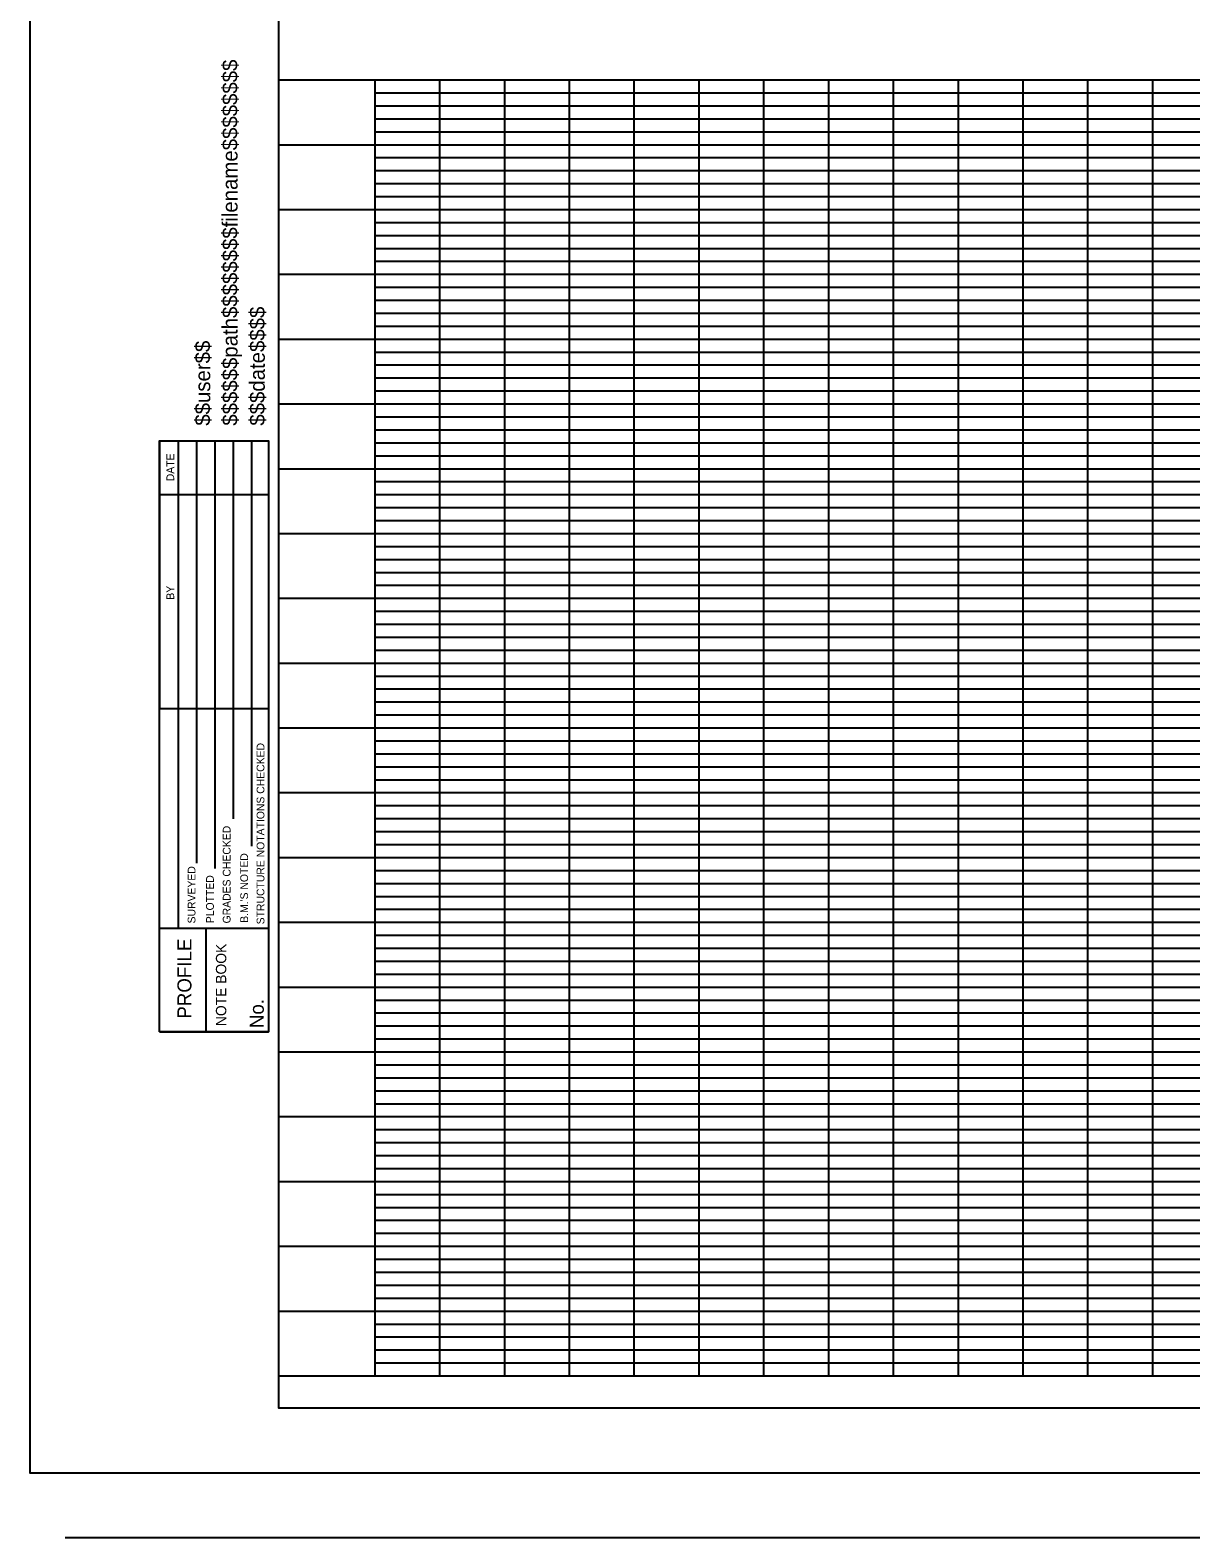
# Model space of a CAD drawing. Extents: x -183 to 1613, y -563 to 588.
# Drawn here: x -183 to 265, y -563 to 19 of the extents above; entities that cross this region are included whole.
import ezdxf

# ---------------------------------------------------------------- set-up
doc = ezdxf.new("R2010")
doc.units = 0
for name, color, linetype in [('RD_SHT_Bndy', 7, 'Continuous'), ('RD_SHT_ID', 7, 'Continuous'), ('RD_SHT_Iplotshp', 7, 'Continuous'), ('RD_SHT_MjGrid', 7, 'Continuous'), ('RD_SHT_MnGrid', 7, 'Continuous'), ('RD_SHT_SubGrid', 7, 'Continuous'), ('RD_SHT_TX', 7, 'Continuous')]:
    doc.layers.add(name, color=color, linetype=linetype)

msp = doc.modelspace()

# ---------------------------------------------------------------- linework, layer by layer
at = {"layer": 'RD_SHT_Bndy'}
for p, q in [((-87, 0), (1588, 0)), ((-50, 0), (-50, -500)), ((-132.95, -139.3), (-132.95, -242.5)), ((-125.85, -139.3), (-125.85, -327.25)), ((-118.8, -139.3), (-118.8, -302.2)), ((-111.7, -139.3), (-111.7, -304.2)), ((-104.65, -139.3), (-104.65, -285.1)), ((-97.55, -139.3), (-97.55, -295.65)), ((-132.95, -159.95), (-90.95, -159.95)), ((-132.95, -242.5), (-90.95, -242.5)), ((-132.95, -327.3), (-90.95, -327.3)), ((-132.95, -367.3), (-132.95, -327.3)), ((-114.95, -367.3), (-114.95, -327.3)), ((-132.95, -367.3), (-90.95, -367.3)), ((-87, -500), (1588, -500)), ((1590.65, -537.5), (-169.35, -537.5)), ((1590.65, -562.5), (-169.35, -562.5))]:
    msp.add_line(p, q, dxfattribs=at)
for points in [[(-86.95, 537.5), (1588, 537.5), (1588, -512.5), (-86.95, -512.5)], [(-132.95, -367.3), (-132.95, -139.3), (-90.95, -139.3), (-90.95, -367.3)]]:
    msp.add_lwpolyline(points, close=True, dxfattribs=at)
at = {"layer": 'RD_SHT_Iplotshp'}
msp.add_lwpolyline([(-182.9, 562.5), (1613, 562.5), (1613, -537.5), (-182.9, -537.5)], close=True, dxfattribs=at)
at = {"layer": 'RD_SHT_MjGrid'}
for p, q in [((0, 0), (0, -500)), ((50, 0), (50, -500)), ((100, 0), (100, -500)), ((150, 0), (150, -500)), ((200, 0), (200, -500)), ((250, 0), (250, -500)), ((-87, -50), (1588, -50)), ((-87, -100), (1588, -100)), ((-87, -150), (1588, -150)), ((-87, -200), (1588, -200)), ((-87, -250), (1588, -250)), ((-87, -300), (1588, -300)), ((-87, -350), (1588, -350)), ((-87, -400), (1588, -400)), ((-87, -450), (1588, -450))]:
    msp.add_line(p, q, dxfattribs=at)
at = {"layer": 'RD_SHT_MnGrid'}
for p, q in [((-25, 0), (-25, -500)), ((25, 0), (25, -500)), ((75, 0), (75, -500)), ((125, 0), (125, -500)), ((175, 0), (175, -500)), ((225, 0), (225, -500)), ((-87, -25), (1588, -25)), ((-87, -75), (1588, -75)), ((-87, -125), (1588, -125)), ((-87, -175), (1588, -175)), ((-87, -225), (1588, -225)), ((-87, -275), (1588, -275)), ((-87, -325), (1588, -325)), ((-87, -375), (1588, -375)), ((-87, -425), (1588, -425)), ((-87, -475), (1588, -475))]:
    msp.add_line(p, q, dxfattribs=at)
at = {"layer": 'RD_SHT_SubGrid'}
for p, q in [((-49.95, -5), (1549.8, -5)), ((-49.95, -10), (1549.25, -10)), ((-49.95, -15), (1549.8, -15)), ((-49.9, -20), (1549.8, -20)), ((-49.95, -30), (1549.8, -30)), ((-49.95, -35), (1548.75, -35)), ((-49.95, -40), (1549.25, -40)), ((-49.95, -45), (1549.8, -45)), ((-49.95, -55), (1549.8, -55)), ((-49.95, -60), (1549.8, -60)), ((-49.95, -65), (1549.25, -65)), ((-49.95, -70), (1549.8, -70)), ((-49.95, -80), (1548.75, -80)), ((-49.95, -85), (1548.75, -85)), ((-49.95, -90), (1549.25, -90)), ((-49.95, -95), (1549.25, -95)), ((-49.95, -105), (1548.75, -105)), ((-49.95, -110), (1549.25, -110)), ((-49.95, -115), (1548.75, -115)), ((-49.9, -120), (1549.8, -120)), ((-49.95, -130), (1549.25, -130)), ((-49.95, -135), (1549.25, -135)), ((-49.95, -140), (1549.25, -140)), ((-49.95, -145), (1549.25, -145)), ((-49.85, -155), (1548.75, -155)), ((-49.85, -160), (1548.75, -160)), ((-49.9, -165), (1549.25, -165)), ((-49.9, -170), (1549.25, -170)), ((-49.95, -180), (1549.25, -180)), ((-49.95, -185), (1549.25, -185)), ((-49.95, -190), (1548.75, -190)), ((-49.95, -195), (1549.25, -195)), ((-49.95, -195), (1549.25, -195)), ((-49.95, -205), (1549.8, -205)), ((-49.95, -210), (1549.8, -210)), ((-49.95, -215), (1549.8, -215)), ((-49.95, -220), (1549.8, -220)), ((-49.95, -230), (1549.8, -230)), ((-49.95, -235), (1549.8, -235)), ((-49.95, -240), (1549.8, -240)), ((-49.95, -245), (1549.8, -245)), ((-49.95, -255), (1549.85, -255)), ((-49.95, -260), (1549.85, -260)), ((-49.95, -265), (1549.85, -265)), ((-49.95, -270), (1549.85, -270)), ((-49.95, -280), (1549.85, -280)), ((-49.95, -285), (1549.85, -285)), ((-49.95, -290), (1549.85, -290)), ((-49.95, -295), (1549.85, -295)), ((-49.95, -305), (1549.85, -305)), ((-49.95, -310), (1549.85, -310)), ((-49.95, -315), (1549.85, -315)), ((-49.95, -320), (1549.85, -320)), ((-49.95, -330), (1549.85, -330)), ((-49.9, -330), (1549.85, -330)), ((-49.95, -335), (1549.85, -335)), ((-49.9, -340), (1549.6, -340)), ((-49.9, -345), (1549.6, -345)), ((-49.95, -360), (1549.95, -360)), ((-49.9, -355), (1549.8, -355)), ((-49.95, -365), (1549.95, -365)), ((-49.9, -370), (1549.95, -370)), ((-49.95, -380), (1549.95, -380)), ((-49.95, -385), (1549.95, -385)), ((-49.95, -390), (1549.95, -390)), ((-49.9, -395), (1549.95, -395)), ((-49.95, -405), (1549.95, -405)), ((-49.95, -410), (1549.95, -410)), ((-49.95, -415), (1549.95, -415)), ((-49.95, -420), (1549.85, -420)), ((-49.9, -430), (1549.6, -430)), ((-49.95, -435), (1549.85, -435)), ((-49.95, -440), (1549.85, -440)), ((-49.95, -445), (1549.85, -445)), ((-49.85, -455), (1549.85, -455)), ((-49.95, -460), (1549.85, -460)), ((-49.95, -465), (1549.85, -465)), ((-49.95, -470), (1549.85, -470)), ((-49.85, -480), (1549.85, -480)), ((-49.85, -485), (1549.85, -485)), ((-49.85, -490), (1549.85, -490)), ((-49.85, -495), (1549.85, -495))]:
    msp.add_line(p, q, dxfattribs=at)

# ---------------------------------------------------------------- texts
at = {"layer": 'RD_SHT_ID'}
for s, p in [('$$$$$$path$$$$$$$$filename$$$$$$$$', (-102.91, -133.42)), ('$$$date$$$$', (-92.39, -133.42)), ('$$user$$', (-113.44, -133.42))]:
    msp.add_text(s, height=5.88, rotation=90, dxfattribs=at).set_placement(p)
at = {"layer": 'RD_SHT_TX'}
for s, height, p in [('DATE', 3, (-127.35, -154.85)), ('BY', 3, (-127.35, -200.55)), ('STRUCTURE NOTATIONS CHECKED', 3, (-92.55, -325.8)), ('GRADES CHECKED', 3, (-105.6, -325.45)), ("B.M.'S NOTED", 3, (-98.85, -325.2)), ('SURVEYED', 3, (-119.15, -325.45)), ('PLOTTED', 3, (-112.05, -325.35)), ('PROFILE', 5.4, (-120.7, -362.2)), ('NOTE BOOK', 4, (-107.25, -365.08)), ('No.', 5.4, (-92.8, -365.85))]:
    msp.add_text(s, height=height, rotation=90, dxfattribs=at).set_placement(p)

doc.saveas('drawing.dxf')
